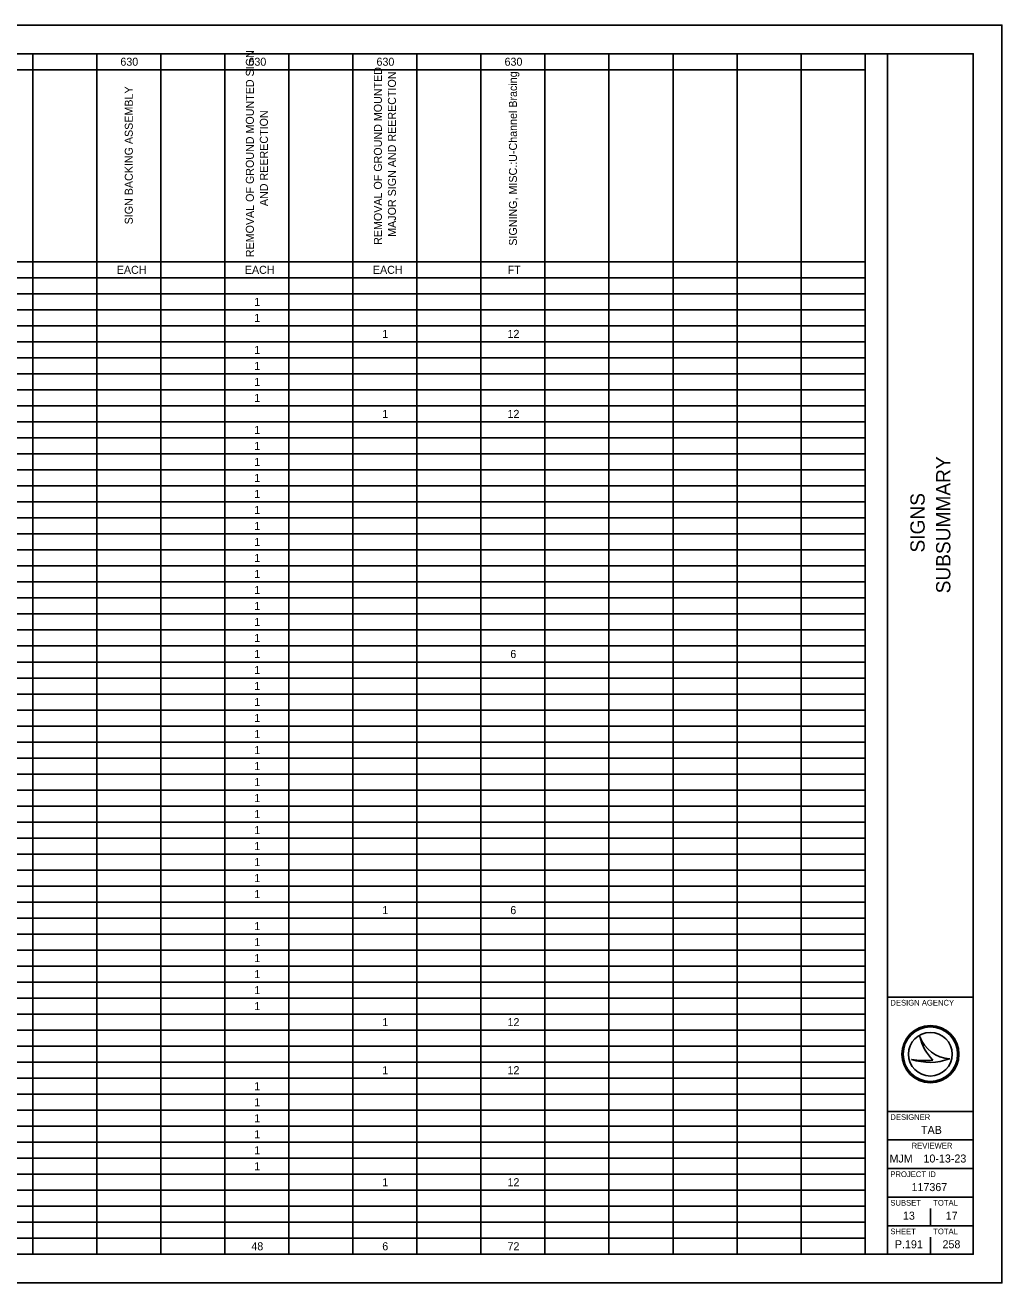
# Model space of a CAD drawing. Extents: x 0 to 34, y 0 to 22.
# Drawn here: x 16.92 to 34, y 0 to 22 of the extents above; entities that cross this region are included whole.
import ezdxf

# ---------------------------------------------------------------- set-up
doc = ezdxf.new("R2010")
doc.units = 0
for name, color, linetype in [('Default', 7, 'Continuous'), ('SH_Border', 7, 'Continuous'), ('SH_Cut_Line', 7, 'Continuous'), ('SH_Data', 7, 'Continuous')]:
    doc.layers.add(name, color=color, linetype=linetype)

msp = doc.modelspace()

# ---------------------------------------------------------------- linework, layer by layer
at = {"layer": 'Default'}
for p, q in [((1.5, 21.5), (31.608, 21.5)), ((17.048, 21.5), (17.048, 0.5)), ((18.168, 21.5), (18.168, 0.5)), ((19.288, 21.5), (19.288, 0.5)), ((20.408, 21.5), (20.408, 0.5)), ((21.528, 21.5), (21.528, 0.5)), ((22.648, 21.5), (22.648, 0.5)), ((23.768, 21.5), (23.768, 0.5)), ((24.888, 21.5), (24.888, 0.5)), ((26.008, 21.5), (26.008, 0.5)), ((27.128, 21.5), (27.128, 0.5)), ((28.248, 21.5), (28.248, 0.5)), ((29.368, 21.5), (29.368, 0.5)), ((30.488, 21.5), (30.488, 0.5)), ((31.608, 21.5), (31.608, 0.5)), ((8.681, 21.22), (31.608, 21.22)), ((8.681, 17.86), (31.608, 17.86)), ((1.5, 17.58), (31.608, 17.58)), ((1.5, 17.3), (31.608, 17.3)), ((1.5, 17.02), (31.608, 17.02)), ((1.5, 16.74), (31.608, 16.74)), ((1.5, 16.46), (31.608, 16.46)), ((1.5, 16.18), (31.608, 16.18)), ((1.5, 15.9), (31.608, 15.9)), ((1.5, 15.62), (31.608, 15.62)), ((1.5, 15.34), (31.608, 15.34)), ((1.5, 15.06), (31.608, 15.06)), ((1.5, 14.78), (31.608, 14.78)), ((1.5, 14.5), (31.608, 14.5)), ((1.5, 14.22), (31.608, 14.22)), ((1.5, 13.94), (31.608, 13.94)), ((1.5, 13.66), (31.608, 13.66)), ((1.5, 13.38), (31.608, 13.38)), ((1.5, 13.1), (31.608, 13.1)), ((1.5, 12.82), (31.608, 12.82)), ((1.5, 12.54), (31.608, 12.54)), ((1.5, 12.26), (31.608, 12.26)), ((1.5, 11.98), (31.608, 11.98)), ((1.5, 11.7), (31.608, 11.7)), ((1.5, 11.42), (31.608, 11.42)), ((1.5, 11.14), (31.608, 11.14)), ((1.5, 10.86), (31.608, 10.86)), ((1.5, 10.58), (31.608, 10.58)), ((1.5, 10.3), (31.608, 10.3)), ((1.5, 10.02), (31.608, 10.02)), ((1.5, 9.74), (31.608, 9.74)), ((1.5, 9.46), (31.608, 9.46)), ((1.5, 9.18), (31.608, 9.18)), ((1.5, 8.9), (31.608, 8.9)), ((1.5, 8.62), (31.608, 8.62)), ((1.5, 8.34), (31.608, 8.34)), ((1.5, 8.06), (31.608, 8.06)), ((1.5, 7.78), (31.608, 7.78)), ((1.5, 7.5), (31.608, 7.5)), ((1.5, 7.22), (31.608, 7.22)), ((1.5, 6.94), (31.608, 6.94)), ((1.5, 6.66), (31.608, 6.66)), ((1.5, 6.38), (31.608, 6.38)), ((1.5, 6.1), (31.608, 6.1)), ((1.5, 5.82), (31.608, 5.82)), ((1.5, 5.54), (31.608, 5.54)), ((1.5, 5.26), (31.608, 5.26)), ((1.5, 4.98), (31.608, 4.98)), ((1.5, 4.7), (31.608, 4.7)), ((1.5, 4.42), (31.608, 4.42)), ((1.5, 4.14), (31.608, 4.14)), ((1.5, 3.86), (31.608, 3.86)), ((1.5, 3.58), (31.608, 3.58)), ((1.5, 3.3), (31.608, 3.3)), ((1.5, 3.02), (31.608, 3.02)), ((1.5, 2.74), (31.608, 2.74)), ((1.5, 2.46), (31.608, 2.46)), ((1.5, 2.18), (31.608, 2.18)), ((1.5, 1.9), (31.608, 1.9)), ((1.5, 1.62), (31.608, 1.62)), ((1.5, 1.34), (31.608, 1.34)), ((1.5, 1.06), (31.608, 1.06)), ((1.5, 0.78), (31.608, 0.78)), ((1.5, 0.5), (31.608, 0.5))]:
    msp.add_line(p, q, dxfattribs=at)
at = {"layer": 'SH_Border'}
for p, q in [((32, 0.5), (32, 21.5)), ((32, 5), (33.5, 5)), ((32, 3), (33.5, 3)), ((32, 2.5), (33.5, 2.5)), ((32, 2), (33.5, 2)), ((32, 1.5), (33.5, 1.5)), ((32, 1), (33.5, 1))]:
    msp.add_line(p, q, dxfattribs=at)
msp.add_lwpolyline([(1.5, 21.5), (33.5, 21.5), (33.5, 0.5), (1.5, 0.5)], close=True, dxfattribs=at)
at = {"layer": 'SH_Cut_Line'}
msp.add_lwpolyline([(0, 0), (34, 0), (34, 22), (0, 22)], close=True, dxfattribs=at)
at = {"layer": 'SH_Data'}
for p, q in [((32.567, 4.31), (32.567, 4.31)), ((32.75, 4), (32.75, 4)), ((32.417, 3.91), (32.417, 3.91)), ((33.087, 3.919), (33.087, 3.919)), ((32.75, 1), (32.75, 1.3)), ((32.375, 0.675), (32.375, 0.675)), ((32.75, 0.5), (32.75, 0.8))]:
    msp.add_line(p, q, dxfattribs=at)
for radius in [0.5, 0.477, 0.477, 0.382]:
    msp.add_circle((32.75, 4), radius, dxfattribs=at)
for centre, radius, start, end in [((33.116, 4.498), 0.58, 198.9257, 198.9319), ((33.347, 4.47), 0.796, 191.6379, 191.6421), ((33.116, 4.498), 0.58, 198.9319, 267.1657), ((33.347, 4.47), 0.796, 191.6421, 226.0947), ((32.739, 4.87), 1.013, 251.4576, 290.0832), ((32.648, 5.154), 1.266, 259.4964, 259.4995), ((32.739, 4.87), 1.013, 251.4527, 251.4576), ((32.648, 5.154), 1.266, 259.4995, 276.6672)]:
    msp.add_arc(centre, radius, start, end, dxfattribs=at)

# ---------------------------------------------------------------- texts
at = {"layer": 'Default'}
for s, p in [('630', (18.581, 21.29)), ('630', (20.821, 21.29)), ('630', (23.061, 21.29)), ('630', (25.301, 21.29)), ('EACH', (18.518, 17.65)), ('EACH', (20.758, 17.65)), ('EACH', (22.998, 17.65)), ('FT', (25.355, 17.65)), ('1', (20.923, 17.09)), ('1', (20.923, 16.81)), ('1', (23.163, 16.53)), ('12', (25.353, 16.53)), ('1', (20.923, 16.25)), ('1', (20.923, 15.97)), ('1', (20.923, 15.69)), ('1', (20.923, 15.41)), ('1', (23.163, 15.13)), ('12', (25.353, 15.13)), ('1', (20.923, 14.85)), ('1', (20.923, 14.57)), ('1', (20.923, 14.29)), ('1', (20.923, 14.01)), ('1', (20.923, 13.73)), ('1', (20.923, 13.45)), ('1', (20.923, 13.17)), ('1', (20.923, 12.89)), ('1', (20.923, 12.61)), ('1', (20.923, 12.33)), ('1', (20.923, 12.05)), ('1', (20.923, 11.77)), ('1', (20.923, 11.49)), ('1', (20.923, 11.21)), ('1', (20.923, 10.93)), ('6', (25.402, 10.93)), ('1', (20.923, 10.65)), ('1', (20.923, 10.37)), ('1', (20.923, 10.09)), ('1', (20.923, 9.81)), ('1', (20.923, 9.53)), ('1', (20.923, 9.25)), ('1', (20.923, 8.97)), ('1', (20.923, 8.69)), ('1', (20.923, 8.41)), ('1', (20.923, 8.13)), ('1', (20.923, 7.85)), ('1', (20.923, 7.57)), ('1', (20.923, 7.29)), ('1', (20.923, 7.01)), ('1', (20.923, 6.73)), ('1', (23.163, 6.45)), ('6', (25.402, 6.45)), ('1', (20.923, 6.17)), ('1', (20.923, 5.89)), ('1', (20.923, 5.61)), ('1', (20.923, 5.33)), ('1', (20.923, 5.05)), ('1', (20.923, 4.77)), ('1', (23.163, 4.49)), ('12', (25.353, 4.49)), ('1', (23.163, 3.65)), ('12', (25.353, 3.65)), ('1', (20.923, 3.37)), ('1', (20.923, 3.09)), ('1', (20.923, 2.81)), ('1', (20.923, 2.53)), ('1', (20.923, 2.25)), ('1', (20.923, 1.97)), ('1', (23.163, 1.69)), ('12', (25.353, 1.69)), ('48', (20.872, 0.57)), ('6', (23.162, 0.57)), ('72', (25.353, 0.57))]:
    msp.add_text(s, height=0.14, dxfattribs=at).set_placement(p)
for s, p in [('REMOVAL OF GROUND MOUNTED SIGN ', (20.916, 17.941)), ('REMOVAL OF GROUND MOUNTED ', (23.156, 18.157)), ('MAJOR SIGN AND REERECTION', (23.401, 18.298)), ('SIGNING, MISC.:U-Channel Bracing', (25.518, 18.143)), ('SIGN BACKING ASSEMBLY', (18.798, 18.515)), ('AND REERECTION', (21.161, 18.835))]:
    msp.add_text(s, height=0.14, rotation=90, dxfattribs=at).set_placement(p)
at = {"layer": 'SH_Data'}
for s, p in [('SUBSUMMARY', (33.1, 12.061)), ('SIGNS', (32.65, 12.775))]:
    msp.add_text(s, height=0.25, rotation=90, dxfattribs=at).set_placement(p)
for s, height, p in [('DESIGN AGENCY', 0.1, (32.05, 4.85)), ('DESIGNER', 0.1, (32.05, 2.85)), ('TAB', 0.14, (32.586, 2.605)), ('REVIEWER', 0.1, (32.422, 2.35)), ('MJM', 0.14, (32.035, 2.105)), ('10-13-23', 0.14, (32.629, 2.105)), ('PROJECT ID', 0.1, (32.05, 1.85)), ('117367', 0.14, (32.42, 1.605)), ('SUBSET', 0.1, (32.05, 1.35)), ('TOTAL', 0.1, (32.8, 1.35)), ('13', 0.14, (32.27, 1.105)), ('17', 0.14, (33.018, 1.105)), ('SHEET', 0.1, (32.05, 0.85)), ('TOTAL', 0.1, (32.8, 0.85)), ('P.191', 0.14, (32.129, 0.605)), ('258', 0.14, (32.962, 0.605))]:
    msp.add_text(s, height=height, dxfattribs=at).set_placement(p)

doc.saveas('drawing.dxf')
